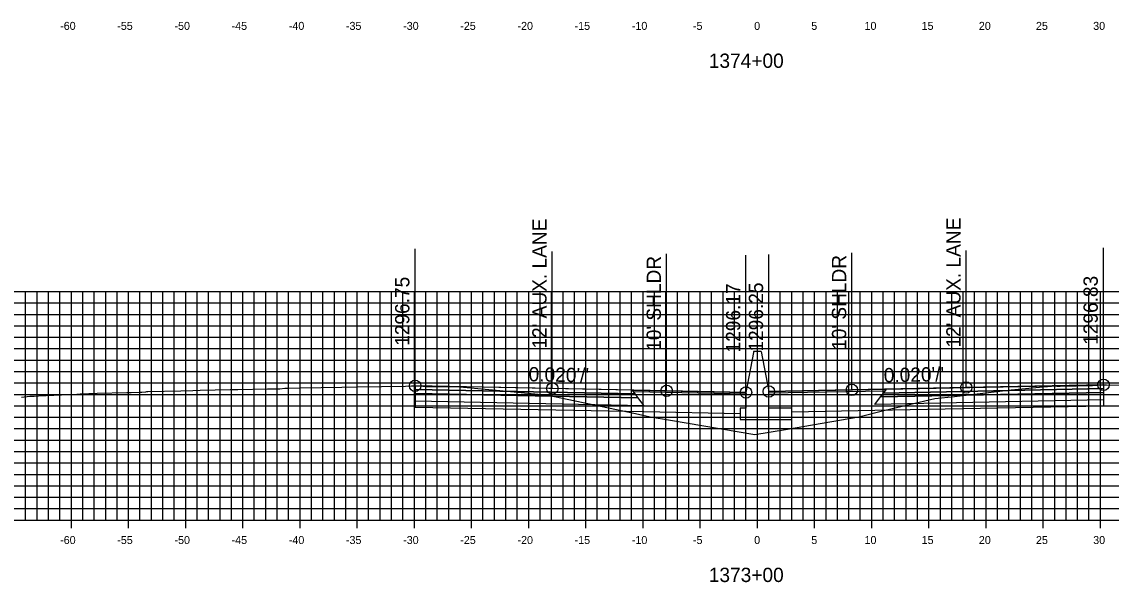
# Model space of a CAD drawing. Extents: x 674939 to 678919, y 750652 to 765176.
# Drawn here: x 678674.2 to 678769.5, y 754717.1 to 754766.2 of the extents above; entities that cross this region are included whole.
import ezdxf

# ---------------------------------------------------------------- set-up
doc = ezdxf.new("R2010")
doc.units = 0
for name, color, linetype in [('Level 10', 7, 'Continuous'), ('Level 17', 7, 'Continuous'), ('Level 18', 7, 'Continuous'), ('Level 19', 7, 'Continuous'), ('Level 20', 7, 'Continuous'), ('Level 22', 7, 'Continuous'), ('Level 23', 7, 'Continuous'), ('Level 4', 7, 'Continuous'), ('Level 8', 7, 'Continuous'), ('Level 9', 7, 'Continuous')]:
    doc.layers.add(name, color=color, linetype=linetype)

msp = doc.modelspace()

# ---------------------------------------------------------------- linework, layer by layer
at = {"layer": 'Level 10'}
msp.add_lwpolyline([(678674.172, 754733.3), (678674.897, 754733.382), (678675.282, 754733.405), (678675.667, 754733.418), (678679.003, 754733.581), (678679.293, 754733.588), (678680.777, 754733.643), (678683.388, 754733.715), (678683.772, 754733.717), (678684.498, 754733.735), (678684.684, 754733.748), (678685.042, 754733.781), (678685.119, 754733.788), (678685.207, 754733.795), (678688.11, 754733.867), (678689.153, 754733.893), (678689.811, 754733.914), (678692.423, 754733.975), (678693.082, 754733.984), (678695.695, 754734.032), (678696.353, 754734.043), (678696.463, 754734.042), (678696.753, 754734.038), (678697.189, 754734.08), (678697.462, 754734.098), (678698.558, 754734.119), (678702.189, 754734.183), (678703.558, 754734.207), (678707.77, 754734.278), (678708.27, 754734.289), (678708.595, 754734.299), (678708.643, 754734.3), (678708.753, 754734.303), (678708.972, 754734.289), (678709.553, 754734.253), (678710.046, 754734.253), (678711.499, 754734.243), (678711.817, 754734.236), (678712.507, 754734.221), (678717.578, 754733.736), (678720.246, 754733.48), (678727.877, 754731.864), (678729.144, 754731.59), (678730.924, 754731.288), (678738.311, 754730.038), (678740.997, 754730.487), (678747.394, 754731.592), (678749.693, 754732.161), (678754.047, 754733.187), (678755.774, 754733.377), (678760.736, 754733.943), (678763.2, 754734.187), (678764.594, 754734.306), (678764.721, 754734.273), (678765.013, 754734.273), (678766.41, 754734.304), (678767.579, 754734.337), (678767.833, 754734.336), (678768.725, 754734.381), (678768.802, 754734.384), (678768.925, 754734.391), (678769.067, 754734.397), (678770.717, 754734.363)], dxfattribs=at)
at = {"layer": 'Level 17'}
for points in [[(678738.863, 754737.299), (678738.863, 754737.299), (678738.203, 754737.299), (678738.203, 754737.22)], [(678738.863, 754737.299), (678739.533, 754733.799)], [(678738.203, 754737.22), (678737.533, 754733.72)], [(678737.533, 754733.72), (678737.533, 754732.345), (678737.033, 754732.345), (678737.033, 754731.345), (678741.533, 754731.345), (678741.533, 754732.345), (678739.533, 754732.345), (678739.533, 754733.799)]]:
    msp.add_lwpolyline(points, dxfattribs=at)
at = {"layer": 'Level 18'}
for points in [[(678768.802, 754734.384), (678756.802, 754734.144), (678746.802, 754733.944), (678739.533, 754733.799)], [(678737.533, 754733.72), (678730.595, 754733.859), (678720.595, 754734.059), (678708.595, 754734.299)]]:
    msp.add_lwpolyline(points, dxfattribs=at)
for points in [[(678768.802, 754734.384), (678768.802, 754734.054), (678749.552, 754733.669), (678749.802, 754734.004)], [(678708.595, 754734.299), (678708.595, 754733.969), (678727.845, 754733.584), (678727.595, 754733.919)], [(678727.595, 754733.919), (678737.533, 754733.72), (678737.537, 754733.562), (678727.715, 754733.759)], [(678749.683, 754733.845), (678739.533, 754733.642), (678739.533, 754733.799), (678749.802, 754734.004)]]:
    msp.add_lwpolyline(points, close=True, dxfattribs=at)
at = {"layer": 'Level 19'}
for points in [[(678708.595, 754733.969), (678708.595, 754733.639), (678728.095, 754733.249), (678727.845, 754733.584)], [(678708.595, 754733.639), (678708.595, 754732.979), (678728.595, 754732.579), (678728.095, 754733.249)], [(678768.802, 754733.724), (678768.802, 754733.064), (678748.802, 754732.664), (678749.302, 754733.334)], [(678768.802, 754734.054), (678768.802, 754733.724), (678749.302, 754733.334), (678749.552, 754733.669)]]:
    msp.add_lwpolyline(points, close=True, dxfattribs=at)
for points in [[(678708.595, 754732.979), (678708.595, 754732.439), (678728.595, 754732.039), (678737.033, 754731.87)], [(678768.802, 754733.064), (678768.802, 754732.524), (678748.802, 754732.124), (678741.533, 754731.979)]]:
    msp.add_lwpolyline(points, dxfattribs=at)
at = {"layer": 'Level 20'}
for p, q in [((678638.533, 754742.551), (678838.533, 754742.551)), ((678674.533, 754722.551), (678674.533, 754742.551)), ((678675.533, 754722.551), (678675.533, 754742.551)), ((678676.533, 754722.551), (678676.533, 754742.551)), ((678677.533, 754722.551), (678677.533, 754742.551)), ((678678.533, 754722.551), (678678.533, 754742.551)), ((678679.533, 754722.551), (678679.533, 754742.551)), ((678680.533, 754722.551), (678680.533, 754742.551)), ((678681.533, 754722.551), (678681.533, 754742.551)), ((678682.533, 754722.551), (678682.533, 754742.551)), ((678683.533, 754722.551), (678683.533, 754742.551)), ((678684.533, 754722.551), (678684.533, 754742.551)), ((678685.533, 754722.551), (678685.533, 754742.551)), ((678686.533, 754722.551), (678686.533, 754742.551)), ((678687.533, 754722.551), (678687.533, 754742.551)), ((678688.533, 754722.551), (678688.533, 754742.551)), ((678689.533, 754722.551), (678689.533, 754742.551)), ((678690.533, 754722.551), (678690.533, 754742.551)), ((678691.533, 754722.551), (678691.533, 754742.551)), ((678692.533, 754722.551), (678692.533, 754742.551)), ((678693.533, 754722.551), (678693.533, 754742.551)), ((678694.533, 754722.551), (678694.533, 754742.551)), ((678695.533, 754722.551), (678695.533, 754742.551)), ((678696.533, 754722.551), (678696.533, 754742.551)), ((678697.533, 754722.551), (678697.533, 754742.551)), ((678698.533, 754722.551), (678698.533, 754742.551)), ((678699.533, 754722.551), (678699.533, 754742.551)), ((678700.533, 754722.551), (678700.533, 754742.551)), ((678701.533, 754722.551), (678701.533, 754742.551)), ((678702.533, 754722.551), (678702.533, 754742.551)), ((678703.533, 754722.551), (678703.533, 754742.551)), ((678704.533, 754722.551), (678704.533, 754742.551)), ((678705.533, 754722.551), (678705.533, 754742.551)), ((678706.533, 754722.551), (678706.533, 754742.551)), ((678707.533, 754722.551), (678707.533, 754742.551)), ((678708.533, 754722.551), (678708.533, 754742.551)), ((678709.533, 754722.551), (678709.533, 754742.551)), ((678710.533, 754722.551), (678710.533, 754742.551)), ((678711.533, 754722.551), (678711.533, 754742.551)), ((678712.533, 754722.551), (678712.533, 754742.551)), ((678713.533, 754722.551), (678713.533, 754742.551)), ((678714.533, 754722.551), (678714.533, 754742.551)), ((678715.533, 754722.551), (678715.533, 754742.551)), ((678716.533, 754722.551), (678716.533, 754742.551)), ((678717.533, 754722.551), (678717.533, 754742.551)), ((678718.533, 754722.551), (678718.533, 754742.551)), ((678719.533, 754722.551), (678719.533, 754742.551)), ((678720.533, 754722.551), (678720.533, 754742.551)), ((678721.533, 754722.551), (678721.533, 754742.551)), ((678722.533, 754722.551), (678722.533, 754742.551)), ((678723.533, 754722.551), (678723.533, 754742.551)), ((678724.533, 754722.551), (678724.533, 754742.551)), ((678725.533, 754722.551), (678725.533, 754742.551)), ((678726.533, 754722.551), (678726.533, 754742.551)), ((678727.533, 754722.551), (678727.533, 754742.551)), ((678728.533, 754722.551), (678728.533, 754742.551)), ((678729.533, 754722.551), (678729.533, 754742.551)), ((678730.533, 754722.551), (678730.533, 754742.551)), ((678731.533, 754722.551), (678731.533, 754742.551)), ((678732.533, 754722.551), (678732.533, 754742.551)), ((678733.533, 754722.551), (678733.533, 754742.551)), ((678734.533, 754722.551), (678734.533, 754742.551)), ((678735.533, 754722.551), (678735.533, 754742.551)), ((678736.533, 754722.551), (678736.533, 754742.551)), ((678737.533, 754722.551), (678737.533, 754742.551)), ((678738.533, 754722.551), (678738.533, 754742.551)), ((678739.533, 754722.551), (678739.533, 754742.551)), ((678740.533, 754722.551), (678740.533, 754742.551)), ((678741.533, 754722.551), (678741.533, 754742.551)), ((678742.533, 754722.551), (678742.533, 754742.551)), ((678743.533, 754722.551), (678743.533, 754742.551)), ((678744.533, 754722.551), (678744.533, 754742.551)), ((678745.533, 754722.551), (678745.533, 754742.551)), ((678746.533, 754722.551), (678746.533, 754742.551)), ((678747.533, 754722.551), (678747.533, 754742.551)), ((678748.533, 754722.551), (678748.533, 754742.551)), ((678749.533, 754722.551), (678749.533, 754742.551)), ((678750.533, 754722.551), (678750.533, 754742.551)), ((678751.533, 754722.551), (678751.533, 754742.551)), ((678752.533, 754722.551), (678752.533, 754742.551)), ((678753.533, 754722.551), (678753.533, 754742.551)), ((678754.533, 754722.551), (678754.533, 754742.551)), ((678755.533, 754722.551), (678755.533, 754742.551)), ((678756.533, 754722.551), (678756.533, 754742.551)), ((678757.533, 754722.551), (678757.533, 754742.551)), ((678758.533, 754722.551), (678758.533, 754742.551)), ((678759.533, 754722.551), (678759.533, 754742.551)), ((678760.533, 754722.551), (678760.533, 754742.551)), ((678761.533, 754722.551), (678761.533, 754742.551)), ((678762.533, 754722.551), (678762.533, 754742.551)), ((678763.533, 754722.551), (678763.533, 754742.551)), ((678764.533, 754722.551), (678764.533, 754742.551)), ((678765.533, 754722.551), (678765.533, 754742.551)), ((678766.533, 754722.551), (678766.533, 754742.551)), ((678767.533, 754722.551), (678767.533, 754742.551)), ((678768.533, 754722.551), (678768.533, 754742.551)), ((678638.533, 754741.551), (678838.533, 754741.551)), ((678638.533, 754740.551), (678838.533, 754740.551)), ((678638.533, 754739.551), (678838.533, 754739.551)), ((678638.533, 754738.551), (678838.533, 754738.551)), ((678638.533, 754737.551), (678838.533, 754737.551)), ((678638.533, 754736.551), (678838.533, 754736.551)), ((678638.533, 754735.551), (678838.533, 754735.551)), ((678638.533, 754734.551), (678838.533, 754734.551)), ((678638.533, 754733.551), (678838.533, 754733.551)), ((678638.533, 754732.551), (678838.533, 754732.551)), ((678638.533, 754731.551), (678838.533, 754731.551)), ((678638.533, 754730.551), (678838.533, 754730.551)), ((678638.533, 754729.551), (678838.533, 754729.551)), ((678638.533, 754728.551), (678838.533, 754728.551)), ((678638.533, 754727.551), (678838.533, 754727.551)), ((678638.533, 754726.551), (678838.533, 754726.551)), ((678638.533, 754725.551), (678838.533, 754725.551)), ((678638.533, 754724.551), (678838.533, 754724.551)), ((678638.533, 754723.551), (678838.533, 754723.551)), ((678638.533, 754722.551), (678838.533, 754722.551))]:
    msp.add_line(p, q, dxfattribs=at)
at = {"layer": 'Level 23'}
for p, q in [((678708.595, 754734.299), (678708.595, 754746.299)), ((678720.595, 754734.059), (678720.595, 754746.059)), ((678730.595, 754733.859), (678730.595, 754745.859)), ((678746.802, 754733.944), (678746.802, 754745.944)), ((678756.802, 754734.144), (678756.802, 754746.144)), ((678768.802, 754734.384), (678768.802, 754746.384)), ((678737.533, 754733.72), (678737.533, 754745.72)), ((678739.533, 754733.799), (678739.533, 754745.799))]:
    msp.add_line(p, q, dxfattribs=at)
at = {"layer": 'Level 4'}
for centre in [(678708.595, 754734.299), (678720.595, 754734.059), (678746.802, 754733.944), (678756.802, 754734.144), (678768.802, 754734.384), (678730.595, 754733.859), (678737.533, 754733.72), (678739.533, 754733.799)]:
    msp.add_circle(centre, 0.5, dxfattribs=at)
at = {"layer": 'Level 8'}
for p, q in [((678678.533, 754721.851), (678678.533, 754723.251)), ((678683.533, 754721.851), (678683.533, 754723.251)), ((678688.533, 754721.851), (678688.533, 754723.251)), ((678693.533, 754721.851), (678693.533, 754723.251)), ((678698.533, 754721.851), (678698.533, 754723.251)), ((678703.533, 754721.851), (678703.533, 754723.251)), ((678708.533, 754721.851), (678708.533, 754723.251)), ((678713.533, 754721.851), (678713.533, 754723.251)), ((678718.533, 754721.851), (678718.533, 754723.251)), ((678723.533, 754721.851), (678723.533, 754723.251)), ((678728.533, 754721.851), (678728.533, 754723.251)), ((678733.533, 754721.851), (678733.533, 754723.251)), ((678738.533, 754721.851), (678738.533, 754723.251)), ((678743.533, 754721.851), (678743.533, 754723.251)), ((678748.533, 754721.851), (678748.533, 754723.251)), ((678753.533, 754721.851), (678753.533, 754723.251)), ((678758.533, 754721.851), (678758.533, 754723.251)), ((678763.533, 754721.851), (678763.533, 754723.251)), ((678768.533, 754721.851), (678768.533, 754723.251)), ((678638.533, 754722.551), (678838.533, 754722.551))]:
    msp.add_line(p, q, dxfattribs=at)

# ---------------------------------------------------------------- texts
at = {"layer": 'Level 22'}
for rotation, p in [(358.85424, (678718.514, 754734.7)), (1.14576, (678749.594, 754734.6))]:
    msp.add_text("0.020'/'", height=1.25, rotation=rotation, dxfattribs=at).set_placement(p)
at = {"layer": 'Level 23'}
for s, p in [("12' AUX. LANE", (678720.095, 754737.559)), ("12' AUX. LANE", (678756.302, 754737.644)), ("10' SHLDR", (678730.095, 754737.359)), ("10' SHLDR", (678746.302, 754737.444)), ('1296.75', (678708.095, 754737.799)), ('1296.17', (678737.033, 754737.22)), ('1296.25', (678739.033, 754737.299)), ('1296.83', (678768.302, 754737.884))]:
    msp.add_text(s, height=1.25, rotation=90, dxfattribs=at).set_placement(p)
at = {"layer": 'Level 9'}
for s, height, p in [('-60', 0.7, (678677.552, 754765.451)), ('-55', 0.7, (678682.546, 754765.451)), ('-50', 0.7, (678687.552, 754765.451)), ('-45', 0.7, (678692.546, 754765.451)), ('-40', 0.7, (678697.552, 754765.451)), ('-35', 0.7, (678702.546, 754765.451)), ('-30', 0.7, (678707.552, 754765.451)), ('-25', 0.7, (678712.546, 754765.451)), ('-20', 0.7, (678717.552, 754765.451)), ('-15', 0.7, (678722.546, 754765.451)), ('-10', 0.7, (678727.552, 754765.451)), ('-5', 0.7, (678732.896, 754765.451)), ('0', 0.7, (678738.252, 754765.451)), ('5', 0.7, (678743.246, 754765.451)), ('10', 0.7, (678747.902, 754765.451)), ('15', 0.7, (678752.896, 754765.451)), ('20', 0.7, (678757.902, 754765.451)), ('25', 0.7, (678762.896, 754765.451)), ('30', 0.7, (678767.902, 754765.451)), ('1374+00', 1.25, (678734.281, 754762.126)), ('-60', 0.7, (678677.552, 754720.451)), ('-55', 0.7, (678682.546, 754720.451)), ('-50', 0.7, (678687.552, 754720.451)), ('-45', 0.7, (678692.546, 754720.451)), ('-40', 0.7, (678697.552, 754720.451)), ('-35', 0.7, (678702.546, 754720.451)), ('-30', 0.7, (678707.552, 754720.451)), ('-25', 0.7, (678712.546, 754720.451)), ('-20', 0.7, (678717.552, 754720.451)), ('-15', 0.7, (678722.546, 754720.451)), ('-10', 0.7, (678727.552, 754720.451)), ('-5', 0.7, (678732.896, 754720.451)), ('0', 0.7, (678738.252, 754720.451)), ('5', 0.7, (678743.246, 754720.451)), ('10', 0.7, (678747.902, 754720.451)), ('15', 0.7, (678752.896, 754720.451)), ('20', 0.7, (678757.902, 754720.451)), ('25', 0.7, (678762.896, 754720.451)), ('30', 0.7, (678767.902, 754720.451)), ('1373+00', 1.25, (678734.281, 754717.126))]:
    msp.add_text(s, height=height, dxfattribs=at).set_placement(p)

doc.saveas('drawing.dxf')
